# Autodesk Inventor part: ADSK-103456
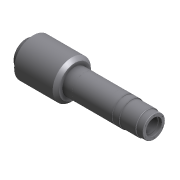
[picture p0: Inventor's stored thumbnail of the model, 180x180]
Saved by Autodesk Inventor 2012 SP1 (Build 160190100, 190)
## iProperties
Shininess: 0.0
Created: 2000-04
Part Number: ADSK-103456
Document SubType Name: Modeling
Stock Number: ADSK-103456
Density: 1 g/cm^3
Material: Default
Density: 0.0
Volumn: 0.0
Area: 0.0
PropertySet Name: Model Information
Control State: 0
Checked Out: False
Master: False
Author: gao
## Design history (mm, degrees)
node "Revolution1" dims "d12" = 360 deg
  sketch "Sketch1"
    geometry: L1 (-33.825, -11.145)-(-33.825, 11.08); L2 (-28.314, -39.72)-(41.343, -39.72); L3 (-33.825, -11.145)-(-33.825, 11.08); L4 (-33.825, 11.08)-(-5.25, 11.08); L5 (-5.25, 11.08)-(-5.25, 36.48) reference; L6 (161.069, 17.43)-(161.069, 36.48); L7 (161.069, 36.48)-(-5.25, 36.48); L8 (-33.825, -11.145)-(475.979, -11.145) reference; L9 (199.169, 10.286)-(199.169, 10.108); L10 (199.169, 10.108)-(328.089, 10.108); L11 (328.089, 10.108)-(328.089, 10.286); L12 (387.079, 10.286)-(387.079, 7.905); L13 (161.069, 10.286)-(199.169, 10.286); L14 (387.079, 7.905)-(450.579, 7.905); L15 (161.069, 10.286)-(161.069, 17.43); L16 (161.069, 36.48)-(161.069, 17.43); L17 (161.069, 36.48)-(161.069, 17.43); L18 (161.069, 36.48)-(161.069, 17.43); L19 (161.069, 17.43)-(161.069, 17.43); L20 (450.579, 7.905)-(450.579, 7.905); L21 (475.979, 4.73)-(475.979, -11.145); L22 (450.579, 7.905)-(450.579, 4.73); L23 (450.579, 4.73)-(475.979, 4.73); L24 (358.529, 10.286)-(358.529, 8.53); L25 (358.529, 8.53)-(361.679, 8.53); L26 (361.679, 8.53)-(361.679, 10.286); L27 (328.089, 10.286)-(358.529, 10.286); L28 (361.679, 10.286)-(387.079, 10.286)
    constraints: 56 end point, 22 perpendicular, 7 parallel, 4 collinear, 2 vertical, 1 horizontal
    dimensions: "d22" = 28.575 distance of L1.end L4.end; "d23" = 50.8 distance between parallel lines of L2 L4; "d24" = 76.2 distance between parallel lines of L2 L7; "d25" = 166.3192 distance of L6.end L5.end; "d50" = 0.1778 distance between parallel lines of L10 L13; "d51" = 50.00625 distance between parallel lines of L2 L13; "d55" = 28.575 distance between parallel lines of L2 L8; "d62" = 47.625 distance between parallel lines of L2 L14; "d75" = 0 distance of L6.start L15.end; "d76" = 57.15 distance between parallel lines of L2 L19; "d78" = 63.5 distance of L12.end L14.end; "d103" = 38.1 horizontal distance of L9.end L13.start; "d152" = 44.45 distance between parallel lines of L2 L23; "d153" = 25.4 distance of L22.end L21.start; "d154" = 3.15 distance of L24.end L25.end; "d156" = 48.25 distance between parallel lines of L2 L25; "d187" = 25.4 distance of L26.end L12.start; "d188" = 30.44043 distance of L11.end L24.start; "d189" = 197.4596 distance of L13.start L24.start
node "Hole3" dims "d66" = 7.7978, "d67" = 15.875, "d68" = 9.525, "d69" = 60 deg, "d70" = 50.8, "d71" = 118 deg, "d190" = 44.45
  sketch "Sketch4" dims "d23" = 50.8, "d64" = 123.825
    geometry: C1 r 50.8 at (0, 0) reference; C2 r 28.575 at (0, 0) reference; 2 further points
    constraints: 1 coincident, 1 vertical alignment, 2 other
    dimensions: "d65" = 0 horizontal distance of C1.centre point (0, 61.913)
node "Circular Pattern2" dims "d72" = 80, "d74" = 45 deg
workplane "Work Plane2"
node "Sketch7"
workplane "Work Plane4"
node "Chamfer3" dims "d157" = 12.7, "d158" = 12.7, "d193" = 45 deg
node "Extrusion3" dims "d160" = 12.7, "d161" = 0
  sketch "Sketch15"
    geometry: C1 r 28.575 at (0, 0) reference; C2 r 44.45 at (0, 0) reference; C3 r 31.75 at (0, 0)
    constraints: 1 centre point, 1 coincident
    dimensions: "d159" = 63.5 diameter of C3
node "Hole11" dims "d163" = 3.683, "d164" = 9.525, "d165" = 6.35, "d166" = 60 deg, "d167" = 19.05, "d168" = 118 deg, "d191" = 12.7
  sketch "Sketch16" dims "d162" = 76.2
    geometry: C1 r 44.45 at (0, 0) reference; 2 further points
    constraints: 1 coincident, 1 vertical alignment, 2 other
node "Circular Pattern4" dims "d169" = 60, "d171" = 60 deg
node "Extrusion4" dims "d173" = 12.7, "d174" = 0
  sketch "Sketch17"
    geometry: C1 r 28.575 at (0, 0) reference; C2 r 31.75 at (0, 0)
    constraints: 1 centre point, 1 coincident
    dimensions: "d172" = 63.5 diameter of C2
node "Hole12" dims "d176" = 3.683, "d177" = 9.525, "d178" = 6.35, "d179" = 60 deg, "d180" = 19.05, "d181" = 118 deg, "d192" = 12.7
  sketch "Sketch18" dims "d175" = 76.2
    geometry: C1 r 50.8 at (0, 0) reference; 2 further points
    constraints: 1 coincident, 1 vertical alignment, 2 other
node "Circular Pattern5" dims "d182" = 60, "d184" = 60 deg
node "Chamfer4" dims "d185" = 1.016, "d186" = 1.016, "d194" = 45 deg
body "Solid1"
other parameters: "d4" = 50.00625, "d16" = 50.00625, "d61" = 50.00625, "d77" = 47.625
